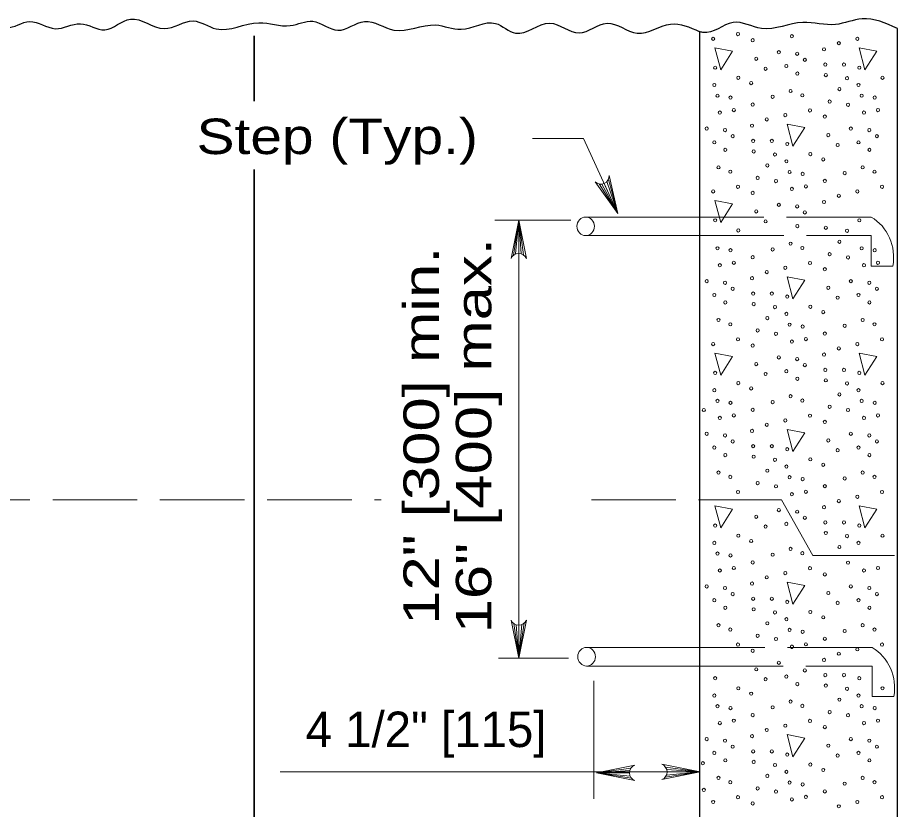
# Model space of a CAD drawing. Extents: x 1083.1 to 1117.1, y 697.4 to 719.4.
# Drawn here: x 1095.658 to 1099.53, y 707.048 to 710.532 of the extents above; entities that cross this region are included whole.
import ezdxf
from ezdxf.enums import TextEntityAlignment as Align

# ---------------------------------------------------------------- set-up
doc = ezdxf.new("R2010")
doc.units = 0
doc.header["$LTSCALE"] = 0.062
doc.linetypes.add('LONG_DASHED', pattern=[7.5, 6, -1.5])
doc.layers.add('1', color=7, linetype='Continuous', lineweight=13)

msp = doc.modelspace()

# ---------------------------------------------------------------- linework, layer by layer
at = {"layer": '1', "lineweight": 25}
for p, q in [((1098.65942, 710.471), (1098.65942, 703.65408)), ((1099.52967, 700.32125), (1099.52967, 710.48467))]:
    msp.add_line(p, q, dxfattribs=at)
at = {"layer": '1', "lineweight": 35}
for p, q in [((1096.69883, 710.45192), (1096.69883, 710.1645)), ((1096.69883, 709.86442), (1096.69883, 708.37567))]:
    msp.add_line(p, q, dxfattribs=at)
at = {"layer": '1'}
for p, q in [((1098.21767, 709.80017), (1098.30008, 709.67033)), ((1098.22942, 709.79983), (1098.30008, 709.67033)), ((1098.23983, 709.80292), (1098.30008, 709.67033)), ((1098.25117, 709.811), (1098.30008, 709.67033)), ((1098.25775, 709.82042), (1098.30008, 709.67033)), ((1098.65342, 709.65483), (1098.15775, 709.65483)), ((1097.75842, 709.64033), (1098.09217, 709.64033)), ((1097.83958, 709.48625), (1097.86317, 709.64033)), ((1097.8495, 709.49208), (1097.86317, 709.64033)), ((1097.86317, 709.49475), (1097.86317, 709.64033)), ((1097.87392, 709.49317), (1097.86317, 709.64033)), ((1097.8845, 709.488), (1097.86317, 709.64033)), ((1097.86317, 707.71325), (1097.86317, 709.64033)), ((1098.15775, 709.57283), (1098.65742, 709.57283)), ((1097.84183, 707.86558), (1097.86317, 707.71325)), ((1097.88675, 707.86733), (1097.86317, 707.71325)), ((1097.85242, 707.86042), (1097.86317, 707.71325)), ((1097.87683, 707.8615), (1097.86317, 707.71325)), ((1097.86317, 707.85883), (1097.86317, 707.71325)), ((1098.65942, 707.76092), (1098.16192, 707.76092)), ((1097.77383, 707.71325), (1098.082, 707.71325)), ((1098.16192, 707.67892), (1098.65533, 707.67892)), ((1098.19383, 707.09442), (1098.19383, 707.61367)), ((1096.81375, 707.21283), (1098.66158, 707.21283)), ((1098.35775, 707.22975), (1098.2055, 707.2085)), ((1098.35258, 707.21925), (1098.2055, 707.2085)), ((1098.35108, 707.2085), (1098.2055, 707.2085)), ((1098.35375, 707.19475), (1098.2055, 707.2085)), ((1098.35958, 707.18492), (1098.2055, 707.2085)), ((1098.5075, 707.18925), (1098.66158, 707.21283)), ((1098.50925, 707.23417), (1098.66158, 707.21283)), ((1098.51333, 707.19917), (1098.66158, 707.21283)), ((1098.51442, 707.22358), (1098.66158, 707.21283)), ((1098.516, 707.21283), (1098.66158, 707.21283))]:
    msp.add_line(p, q, dxfattribs=at)
at = {"layer": '1', "linetype": 'LONG_DASHED'}
for p, q in [((1099.41417, 709.65483), (1098.65342, 709.65483)), ((1098.65742, 709.57283), (1099.41417, 709.57283)), ((1094.39633, 708.41083), (1097.25833, 708.41083)), ((1098.18292, 708.41083), (1099.0195, 708.41083)), ((1099.0195, 708.41083), (1099.15725, 708.16475)), ((1099.15725, 708.16475), (1099.5175, 708.16475)), ((1099.41833, 707.76092), (1098.65942, 707.76092)), ((1098.65533, 707.67892), (1099.41833, 707.67892))]:
    msp.add_line(p, q, dxfattribs=at)
at = {"layer": '1'}
for points in [[(1098.72675, 710.39933), (1098.75242, 710.30208), (1098.80458, 710.38425)], [(1099.36117, 710.39933), (1099.38675, 710.30208), (1099.439, 710.38425)], [(1099.04392, 710.06358), (1099.06958, 709.96625), (1099.12183, 710.04842)], [(1098.72675, 709.72775), (1098.75242, 709.63033), (1098.80458, 709.71258)], [(1099.04392, 709.392), (1099.06958, 709.29458), (1099.12183, 709.37675)], [(1098.72675, 709.05608), (1098.75242, 708.95875), (1098.80458, 709.04092)], [(1099.36117, 709.05608), (1099.38675, 708.95875), (1099.439, 709.04092)], [(1099.04392, 708.72025), (1099.06958, 708.623), (1099.12183, 708.70517)], [(1098.72675, 708.3845), (1098.75242, 708.28717), (1098.80458, 708.36925)], [(1099.36117, 708.3845), (1099.38675, 708.28717), (1099.439, 708.36925)], [(1099.04392, 708.04867), (1099.06958, 707.95125), (1099.12183, 708.03342)], [(1099.04392, 707.377), (1099.06958, 707.27967), (1099.12183, 707.36183)]]:
    msp.add_lwpolyline(points, close=True, dxfattribs=at)
for points in [[(1098.30008, 709.67033), (1098.14858, 709.99992), (1097.92408, 709.99992)], [(1098.26108, 709.83742), (1098.30008, 709.67033), (1098.19983, 709.80958)], [(1097.8295, 709.47208), (1097.86317, 709.64033), (1097.89683, 709.47208)], [(1097.89683, 707.8815), (1097.86317, 707.71325), (1097.8295, 707.8815)], [(1098.49333, 707.17917), (1098.66158, 707.21283), (1098.49333, 707.2465)], [(1098.37367, 707.17483), (1098.2055, 707.2085), (1098.37367, 707.24208)]]:
    msp.add_lwpolyline(points, dxfattribs=at)
at = {"layer": '1', "linetype": 'LONG_DASHED'}
for points in [[(1099.41417, 709.57283), (1099.41417, 709.43892), (1099.50983, 709.43892)], [(1099.41833, 707.67892), (1099.41833, 707.545), (1099.514, 707.545)]]:
    msp.add_lwpolyline(points, dxfattribs=at)
at = {"layer": '1', "lineweight": 35}
msp.add_lwpolyline([(1096.69883, 708.37567), (1096.69883, 700.00317), (1096.69883, 699.45117)], dxfattribs=at)
at = {"layer": '1'}
for centre, start, end in [((1098.22483, 709.83586), 226.51945, 2.34557), ((1097.86321, 709.45851), 22.08782, 157.91395), ((1097.86313, 707.89506), 202.08782, 337.91395), ((1098.47974, 707.21286), 292.08605, 67.91218), ((1098.38728, 707.20851), 112.08782, 247.91395)]:
    msp.add_arc(centre, 0.03631, start, end, dxfattribs=at)
for centre, major_axis in [((1098.82781, 710.45979), (0, 0.00718)), ((1098.71906, 710.43891), (0, 0.00718)), ((1098.89294, 710.43259), (0, 0.00718)), ((1099.06534, 710.45011), (0, 0.00718)), ((1099.27205, 710.41988), (0, 0.00718)), ((1099.35346, 710.43891), (0, 0.00718)), ((1099.00771, 710.38003), (0, 0.00718)), ((1099.08855, 710.37304), (0, 0.00718)), ((1099.20702, 710.39268), (0, 0.00718)), ((1098.90838, 710.35098), (0, 0.00718)), ((1099.12222, 710.34645), (0, 0.00718)), ((1098.72763, 710.31197), (0, 0.00718)), ((1098.94951, 710.30744), (0, 0.00718)), ((1099.04113, 710.31925), (0, 0.00718)), ((1099.21215, 710.32557), (0, 0.00718)), ((1099.29441, 710.32557), (0, 0.00718)), ((1099.36203, 710.31197), (0, 0.00718)), ((1098.82955, 710.26753), (0, 0.00718)), ((1099.08939, 710.28628), (0, 0.00718)), ((1099.21469, 710.27934), (0, 0.00718)), ((1099.3081, 710.26574), (0, 0.00718)), ((1099.46395, 710.26753), (0, 0.00718)), ((1098.72419, 710.2358), (0, 0.00718)), ((1098.88607, 710.24397), (0, 0.00718)), ((1099.35859, 710.2358), (0, 0.00718)), ((1098.73793, 710.18867), (0, 0.00718)), ((1098.79529, 710.18044), (0, 0.00718)), ((1098.98059, 710.18385), (0, 0.00718)), ((1099.05942, 710.20921), (0, 0.00718)), ((1099.11165, 710.19018), (0, 0.00718)), ((1099.27464, 710.21766), (0, 0.00718)), ((1099.37234, 710.18867), (0, 0.00718)), ((1099.4297, 710.18044), (0, 0.00718)), ((1098.89294, 710.1496), (0, 0.00718)), ((1099.23155, 710.16298), (0, 0.00718)), ((1099.31233, 710.14876), (0, 0.00718)), ((1098.74814, 710.11428), (0, 0.00718)), ((1098.80983, 710.1252), (0, 0.00718)), ((1099.03626, 710.10309), (0, 0.00718)), ((1099.14501, 710.12397), (0, 0.00718)), ((1099.38254, 710.11428), (0, 0.00718)), ((1099.44424, 710.1252), (0, 0.00718)), ((1098.95485, 710.08406), (0, 0.00718)), ((1099.21014, 710.09676), (0, 0.00718)), ((1098.69051, 710.04421), (0, 0.00718)), ((1098.77135, 710.03721), (0, 0.00718)), ((1098.88982, 710.05686), (0, 0.00718)), ((1099.32491, 710.04421), (0, 0.00718)), ((1099.40575, 710.03721), (0, 0.00718)), ((1098.80502, 710.01062), (0, 0.00718)), ((1098.89495, 709.98975), (0, 0.00718)), ((1098.97721, 709.98975), (0, 0.00718)), ((1099.22558, 710.01516), (0, 0.00718)), ((1099.43942, 710.01062), (0, 0.00718)), ((1098.72392, 709.98342), (0, 0.00718)), ((1098.77219, 709.95046), (0, 0.00718)), ((1099.04483, 709.97615), (0, 0.00718)), ((1099.26671, 709.97161), (0, 0.00718)), ((1099.35833, 709.98342), (0, 0.00718)), ((1099.40659, 709.95046), (0, 0.00718)), ((1098.89749, 709.94352), (0, 0.00718)), ((1098.9909, 709.92991), (0, 0.00718)), ((1099.14675, 709.93171), (0, 0.00718)), ((1098.74222, 709.87338), (0, 0.00718)), ((1098.95744, 709.88184), (0, 0.00718)), ((1099.04139, 709.89997), (0, 0.00718)), ((1099.20327, 709.90814), (0, 0.00718)), ((1099.37662, 709.87338), (0, 0.00718)), ((1098.79445, 709.85435), (0, 0.00718)), ((1099.05514, 709.85284), (0, 0.00718)), ((1099.1125, 709.84462), (0, 0.00718)), ((1099.29779, 709.84803), (0, 0.00718)), ((1099.42885, 709.85435), (0, 0.00718)), ((1098.91435, 709.82715), (0, 0.00718)), ((1098.99513, 709.81294), (0, 0.00718)), ((1099.21014, 709.81378), (0, 0.00718)), ((1098.71906, 709.76726), (0, 0.00718)), ((1098.82781, 709.78814), (0, 0.00718)), ((1098.89294, 709.76094), (0, 0.00718)), ((1099.06534, 709.77846), (0, 0.00718)), ((1099.12703, 709.78937), (0, 0.00718)), ((1099.35346, 709.76726), (0, 0.00718)), ((1099.46221, 709.78814), (0, 0.00718)), ((1099.20702, 709.72103), (0, 0.00718)), ((1099.27205, 709.74823), (0, 0.00718)), ((1098.90838, 709.67933), (0, 0.00718)), ((1099.00771, 709.70838), (0, 0.00718)), ((1099.08855, 709.70139), (0, 0.00718)), ((1098.15771, 709.61383), (0, -0.041)), ((1098.72763, 709.64032), (0, 0.00718)), ((1099.12222, 709.6748), (0, 0.00718)), ((1099.36203, 709.64032), (0, 0.00718)), ((1098.94951, 709.63579), (0, 0.00718)), ((1099.08939, 709.61463), (0, 0.00718)), ((1099.21469, 709.60769), (0, 0.00718)), ((1098.82955, 709.59588), (0, 0.00718)), ((1099.3081, 709.59409), (0, 0.00718)), ((1099.05942, 709.53756), (0, 0.00718)), ((1099.27464, 709.54601), (0, 0.00718)), ((1098.73793, 709.51702), (0, 0.00718)), ((1098.79529, 709.50879), (0, 0.00718)), ((1098.98059, 709.51221), (0, 0.00718)), ((1099.11165, 709.51853), (0, 0.00718)), ((1099.23155, 709.49133), (0, 0.00718)), ((1099.37234, 709.51702), (0, 0.00718)), ((1099.4297, 709.50879), (0, 0.00718)), ((1098.80983, 709.45355), (0, 0.00718)), ((1098.89294, 709.47795), (0, 0.00718)), ((1099.14501, 709.45232), (0, 0.00718)), ((1099.31233, 709.47711), (0, 0.00718)), ((1099.44424, 709.45355), (0, 0.00718)), ((1098.74814, 709.44263), (0, 0.00718)), ((1098.95485, 709.41241), (0, 0.00718)), ((1099.03626, 709.43144), (0, 0.00718)), ((1099.21014, 709.42511), (0, 0.00718)), ((1099.38254, 709.44263), (0, 0.00718)), ((1098.69051, 709.37256), (0, 0.00718)), ((1098.88982, 709.38521), (0, 0.00718)), ((1099.32491, 709.37256), (0, 0.00718)), ((1098.77135, 709.36556), (0, 0.00718)), ((1098.80502, 709.33898), (0, 0.00718)), ((1099.22558, 709.34351), (0, 0.00718)), ((1099.40575, 709.36556), (0, 0.00718)), ((1099.43942, 709.33898), (0, 0.00718)), ((1098.72392, 709.31177), (0, 0.00718)), ((1098.89495, 709.3181), (0, 0.00718)), ((1098.97721, 709.3181), (0, 0.00718)), ((1099.04483, 709.3045), (0, 0.00718)), ((1099.26671, 709.29996), (0, 0.00718)), ((1099.35833, 709.31177), (0, 0.00718)), ((1098.77219, 709.27881), (0, 0.00718)), ((1098.89749, 709.27187), (0, 0.00718)), ((1098.9909, 709.25827), (0, 0.00718)), ((1099.14675, 709.26006), (0, 0.00718)), ((1099.40659, 709.27881), (0, 0.00718)), ((1099.04139, 709.22832), (0, 0.00718)), ((1099.20327, 709.23649), (0, 0.00718)), ((1098.74222, 709.20174), (0, 0.00718)), ((1098.79445, 709.18271), (0, 0.00718)), ((1098.95744, 709.21019), (0, 0.00718)), ((1099.05514, 709.18119), (0, 0.00718)), ((1099.1125, 709.17297), (0, 0.00718)), ((1099.29779, 709.17638), (0, 0.00718)), ((1099.37662, 709.20174), (0, 0.00718)), ((1099.42885, 709.18271), (0, 0.00718)), ((1098.91435, 709.1555), (0, 0.00718)), ((1098.99513, 709.14129), (0, 0.00718)), ((1099.21014, 709.14213), (0, 0.00718)), ((1098.71906, 709.09561), (0, 0.00718)), ((1098.82781, 709.11649), (0, 0.00718)), ((1099.06534, 709.10681), (0, 0.00718)), ((1099.12703, 709.11772), (0, 0.00718)), ((1099.35346, 709.09561), (0, 0.00718)), ((1099.46221, 709.11649), (0, 0.00718)), ((1098.89294, 709.08929), (0, 0.00718)), ((1099.27205, 709.07658), (0, 0.00718)), ((1099.00771, 709.03673), (0, 0.00718)), ((1099.08855, 709.02974), (0, 0.00718)), ((1099.20702, 709.04938), (0, 0.00718)), ((1098.90838, 709.00768), (0, 0.00718)), ((1099.12222, 709.00315), (0, 0.00718)), ((1099.21215, 708.98227), (0, 0.00718)), ((1099.29441, 708.98227), (0, 0.00718)), ((1098.72763, 708.96867), (0, 0.00718)), ((1098.94951, 708.96414), (0, 0.00718)), ((1099.04113, 708.97595), (0, 0.00718)), ((1099.08939, 708.94298), (0, 0.00718)), ((1099.36203, 708.96867), (0, 0.00718)), ((1098.82955, 708.92423), (0, 0.00718)), ((1099.21469, 708.93604), (0, 0.00718)), ((1099.3081, 708.92244), (0, 0.00718)), ((1099.46395, 708.92423), (0, 0.00718)), ((1098.72419, 708.8925), (0, 0.00718)), ((1098.88607, 708.90067), (0, 0.00718)), ((1099.05942, 708.86591), (0, 0.00718)), ((1099.27464, 708.87436), (0, 0.00718)), ((1099.35859, 708.8925), (0, 0.00718)), ((1098.73793, 708.84537), (0, 0.00718)), ((1098.79529, 708.83714), (0, 0.00718)), ((1098.98059, 708.84056), (0, 0.00718)), ((1099.11165, 708.84688), (0, 0.00718)), ((1099.37234, 708.84537), (0, 0.00718)), ((1099.4297, 708.83714), (0, 0.00718)), ((1098.67793, 708.80546), (0, 0.00718)), ((1098.89294, 708.8063), (0, 0.00718)), ((1099.23155, 708.81968), (0, 0.00718)), ((1099.31233, 708.80546), (0, 0.00718)), ((1098.74814, 708.77098), (0, 0.00718)), ((1098.80983, 708.7819), (0, 0.00718)), ((1099.03626, 708.75979), (0, 0.00718)), ((1099.14501, 708.78067), (0, 0.00718)), ((1099.21014, 708.75347), (0, 0.00718)), ((1099.38254, 708.77098), (0, 0.00718)), ((1099.44424, 708.7819), (0, 0.00718)), ((1098.88982, 708.71356), (0, 0.00718)), ((1098.95485, 708.74076), (0, 0.00718)), ((1098.69051, 708.70091), (0, 0.00718)), ((1098.77135, 708.69391), (0, 0.00718)), ((1099.22558, 708.67186), (0, 0.00718)), ((1099.32491, 708.70091), (0, 0.00718)), ((1099.40575, 708.69391), (0, 0.00718)), ((1098.72392, 708.64012), (0, 0.00718)), ((1098.80502, 708.66733), (0, 0.00718)), ((1098.89495, 708.64645), (0, 0.00718)), ((1098.97721, 708.64645), (0, 0.00718)), ((1099.04483, 708.63285), (0, 0.00718)), ((1099.35833, 708.64012), (0, 0.00718)), ((1099.43942, 708.66733), (0, 0.00718)), ((1098.77219, 708.60716), (0, 0.00718)), ((1098.89749, 708.60022), (0, 0.00718)), ((1099.26671, 708.62831), (0, 0.00718)), ((1099.40659, 708.60716), (0, 0.00718)), ((1098.9909, 708.58662), (0, 0.00718)), ((1099.04139, 708.55667), (0, 0.00718)), ((1099.14675, 708.58841), (0, 0.00718)), ((1099.20327, 708.56484), (0, 0.00718)), ((1098.74222, 708.53009), (0, 0.00718)), ((1098.95744, 708.53854), (0, 0.00718)), ((1099.37662, 708.53009), (0, 0.00718)), ((1098.79445, 708.51106), (0, 0.00718)), ((1098.91435, 708.48385), (0, 0.00718)), ((1099.05514, 708.50954), (0, 0.00718)), ((1099.1125, 708.50132), (0, 0.00718)), ((1099.29779, 708.50473), (0, 0.00718)), ((1099.42885, 708.51106), (0, 0.00718)), ((1098.82781, 708.44484), (0, 0.00718)), ((1098.99513, 708.46964), (0, 0.00718)), ((1099.12703, 708.44607), (0, 0.00718)), ((1099.21014, 708.47048), (0, 0.00718)), ((1099.46221, 708.44484), (0, 0.00718)), ((1099.06534, 708.43516), (0, 0.00718)), ((1099.27205, 708.40494), (0, 0.00718)), ((1099.35346, 708.42397), (0, 0.00718)), ((1099.00771, 708.36508), (0, 0.00718)), ((1099.20702, 708.37773), (0, 0.00718)), ((1098.90838, 708.33604), (0, 0.00718)), ((1099.08855, 708.35809), (0, 0.00718)), ((1099.12222, 708.3315), (0, 0.00718)), ((1098.72763, 708.29702), (0, 0.00718)), ((1098.94951, 708.29249), (0, 0.00718)), ((1099.04113, 708.3043), (0, 0.00718)), ((1099.21215, 708.31062), (0, 0.00718)), ((1099.29441, 708.31062), (0, 0.00718)), ((1099.36203, 708.29702), (0, 0.00718)), ((1098.82955, 708.25258), (0, 0.00718)), ((1099.21469, 708.26439), (0, 0.00718)), ((1099.3081, 708.25079), (0, 0.00718)), ((1099.46395, 708.25258), (0, 0.00718)), ((1098.72419, 708.22085), (0, 0.00718)), ((1098.88607, 708.22902), (0, 0.00718)), ((1099.35859, 708.22085), (0, 0.00718)), ((1098.73793, 708.17372), (0, 0.00718)), ((1098.98059, 708.16891), (0, 0.00718)), ((1099.05942, 708.19426), (0, 0.00718)), ((1099.11165, 708.17523), (0, 0.00718)), ((1099.27464, 708.20271), (0, 0.00718)), ((1098.79529, 708.16549), (0, 0.00718)), ((1098.89294, 708.13465), (0, 0.00718)), ((1099.31233, 708.13381), (0, 0.00718)), ((1098.74814, 708.09934), (0, 0.00718)), ((1098.80983, 708.11025), (0, 0.00718)), ((1099.14501, 708.10902), (0, 0.00718)), ((1099.38254, 708.09934), (0, 0.00718)), ((1099.44424, 708.11025), (0, 0.00718)), ((1098.95485, 708.06911), (0, 0.00718)), ((1099.03626, 708.08814), (0, 0.00718)), ((1099.21014, 708.08182), (0, 0.00718)), ((1098.69051, 708.02926), (0, 0.00718)), ((1098.77135, 708.02226), (0, 0.00718)), ((1098.88982, 708.04191), (0, 0.00718)), ((1099.32491, 708.02926), (0, 0.00718)), ((1099.40575, 708.02226), (0, 0.00718)), ((1098.80502, 707.99568), (0, 0.00718)), ((1098.89495, 707.9748), (0, 0.00718)), ((1098.97721, 707.9748), (0, 0.00718)), ((1099.22558, 708.00021), (0, 0.00718)), ((1099.43942, 707.99568), (0, 0.00718)), ((1098.72392, 707.96848), (0, 0.00718)), ((1098.77219, 707.93551), (0, 0.00718)), ((1099.04483, 707.9612), (0, 0.00718)), ((1099.26671, 707.95667), (0, 0.00718)), ((1099.35833, 707.96848), (0, 0.00718)), ((1099.40659, 707.93551), (0, 0.00718)), ((1098.89749, 707.92857), (0, 0.00718)), ((1098.9909, 707.91497), (0, 0.00718)), ((1099.14675, 707.91676), (0, 0.00718)), ((1098.74222, 707.85844), (0, 0.00718)), ((1098.95744, 707.86689), (0, 0.00718)), ((1099.04139, 707.88502), (0, 0.00718)), ((1099.20327, 707.89319), (0, 0.00718)), ((1099.37662, 707.85844), (0, 0.00718)), ((1098.79445, 707.83941), (0, 0.00718)), ((1099.05514, 707.8379), (0, 0.00718)), ((1099.1125, 707.82967), (0, 0.00718)), ((1099.29779, 707.83308), (0, 0.00718)), ((1099.42885, 707.83941), (0, 0.00718)), ((1098.91435, 707.81221), (0, 0.00718)), ((1098.99513, 707.79799), (0, 0.00718)), ((1099.21014, 707.79883), (0, 0.00718)), ((1098.16189, 707.7199), (0, -0.041)), ((1098.82781, 707.77319), (0, 0.00718)), ((1098.89294, 707.74599), (0, 0.00718)), ((1099.12703, 707.77442), (0, 0.00718)), ((1099.35346, 707.75232), (0, 0.00718)), ((1099.46221, 707.77319), (0, 0.00718)), ((1099.20702, 707.70608), (0, 0.00718)), ((1099.27205, 707.73329), (0, 0.00718)), ((1098.90838, 707.66439), (0, 0.00718)), ((1099.00771, 707.69344), (0, 0.00718)), ((1098.72763, 707.62537), (0, 0.00718)), ((1099.04113, 707.63265), (0, 0.00718)), ((1099.12222, 707.65985), (0, 0.00718)), ((1099.21215, 707.63898), (0, 0.00718)), ((1099.29441, 707.63898), (0, 0.00718)), ((1099.36203, 707.62537), (0, 0.00718)), ((1098.94951, 707.62084), (0, 0.00718)), ((1099.08939, 707.59968), (0, 0.00718)), ((1099.21469, 707.59274), (0, 0.00718)), ((1098.72419, 707.5492), (0, 0.00718)), ((1098.82955, 707.58093), (0, 0.00718)), ((1098.88607, 707.55737), (0, 0.00718)), ((1099.3081, 707.57914), (0, 0.00718)), ((1099.35859, 707.5492), (0, 0.00718)), ((1099.46395, 707.58093), (0, 0.00718)), ((1099.05942, 707.52261), (0, 0.00718)), ((1099.27464, 707.53106), (0, 0.00718)), ((1098.73793, 707.50207), (0, 0.00718)), ((1098.79529, 707.49384), (0, 0.00718)), ((1098.98059, 707.49726), (0, 0.00718)), ((1099.11165, 707.50358), (0, 0.00718)), ((1099.23155, 707.47638), (0, 0.00718)), ((1099.37234, 707.50207), (0, 0.00718)), ((1099.4297, 707.49384), (0, 0.00718)), ((1098.80983, 707.4386), (0, 0.00718)), ((1098.89294, 707.463), (0, 0.00718)), ((1099.14501, 707.43737), (0, 0.00718)), ((1099.31233, 707.46216), (0, 0.00718)), ((1099.44424, 707.4386), (0, 0.00718)), ((1098.74814, 707.42769), (0, 0.00718)), ((1098.95485, 707.39746), (0, 0.00718)), ((1099.03626, 707.41649), (0, 0.00718)), ((1099.21014, 707.41017), (0, 0.00718)), ((1099.38254, 707.42769), (0, 0.00718)), ((1098.69051, 707.35761), (0, 0.00718)), ((1098.88982, 707.37026), (0, 0.00718)), ((1099.32491, 707.35761), (0, 0.00718)), ((1098.77135, 707.35061), (0, 0.00718)), ((1098.80502, 707.32403), (0, 0.00718)), ((1099.22558, 707.32856), (0, 0.00718)), ((1099.40575, 707.35061), (0, 0.00718)), ((1099.43942, 707.32403), (0, 0.00718)), ((1098.72392, 707.29683), (0, 0.00718)), ((1098.89495, 707.30315), (0, 0.00718)), ((1098.97721, 707.30315), (0, 0.00718)), ((1099.04483, 707.28955), (0, 0.00718)), ((1099.26671, 707.28502), (0, 0.00718)), ((1099.35833, 707.29683), (0, 0.00718)), ((1098.6737, 707.25095), (0, 0.00718)), ((1098.77219, 707.26386), (0, 0.00718)), ((1098.89749, 707.25692), (0, 0.00718)), ((1098.9909, 707.24332), (0, 0.00718)), ((1099.14675, 707.24511), (0, 0.00718)), ((1099.40659, 707.26386), (0, 0.00718)), ((1099.04139, 707.21337), (0, 0.00718)), ((1099.20327, 707.22155), (0, 0.00718)), ((1098.74222, 707.18679), (0, 0.00718)), ((1098.79445, 707.16776), (0, 0.00718)), ((1098.95744, 707.19524), (0, 0.00718)), ((1099.05514, 707.16625), (0, 0.00718)), ((1099.29779, 707.16143), (0, 0.00718)), ((1099.37662, 707.18679), (0, 0.00718)), ((1099.42885, 707.16776), (0, 0.00718)), ((1098.67793, 707.13398), (0, 0.00718)), ((1098.91435, 707.14056), (0, 0.00718)), ((1098.99513, 707.12634), (0, 0.00718)), ((1099.1125, 707.15802), (0, 0.00718)), ((1099.21014, 707.12718), (0, 0.00718)), ((1098.82781, 707.10154), (0, 0.00718)), ((1099.06534, 707.09186), (0, 0.00718)), ((1099.12703, 707.10278), (0, 0.00718)), ((1099.46221, 707.10154), (0, 0.00718)), ((1098.71906, 707.08067), (0, 0.00718)), ((1098.89294, 707.07434), (0, 0.00718)), ((1099.27205, 707.06164), (0, 0.00718)), ((1099.35346, 707.08067), (0, 0.00718))]:
    msp.add_ellipse(centre, major_axis=major_axis, ratio=0.944544, dxfattribs=at)
at = {"layer": '1', "linetype": 'LONG_DASHED'}
for centre in [(1099.32145, 709.47706), (1099.32563, 707.58312)]:
    msp.add_ellipse(centre, major_axis=(0, -0.20306), ratio=0.944544, start_param=1.3817766, end_param=2.6372404, dxfattribs=at)
msp.add_ellipse((1099.06534, 707.76351), major_axis=(0, 0.00718), ratio=0.944544, dxfattribs=at)
at = {"layer": '1', "lineweight": 25}
for points in [[(1094.78833, 710.5125), (1094.86758, 710.49192), (1095.00183, 710.51783), (1095.11458, 710.47258), (1095.26925, 710.51717), (1095.382, 710.47667), (1095.49667, 710.52592), (1095.60942, 710.4875), (1095.711, 710.51525), (1095.82367, 710.48358), (1095.93467, 710.5055), (1096.04175, 710.47867), (1096.15458, 710.526), (1096.30275, 710.48383), (1096.43042, 710.5175), (1096.53192, 710.48283), (1096.71933, 710.51), (1096.85817, 710.497), (1096.957, 710.516), (1097.06775, 710.4765), (1097.18433, 710.51508), (1097.31383, 710.47767), (1097.49742, 710.49992), (1097.61017, 710.48092), (1097.76117, 710.50692), (1097.84967, 710.4635), (1097.99975, 710.50808), (1098.12925, 710.46475), (1098.25225, 710.50725), (1098.38458, 710.46392), (1098.53183, 710.50358), (1098.65775, 710.47125)], [(1099.52967, 710.48467), (1099.37425, 710.527), (1099.25783, 710.502), (1099.11333, 710.51117), (1098.93158, 710.48492), (1098.80675, 710.51075), (1098.6735, 710.46717), (1098.65775, 710.47125)]]:
    msp.add_spline(points, degree=3, dxfattribs=at)

# ---------------------------------------------------------------- texts
at = {"layer": '1', "width": 1.2}
msp.add_text('Step (Typ.)', height=0.156, dxfattribs=at).set_placement((1096.44558, 709.93183))
at = {"layer": '1', "width": 1.3}
for s, p in [('16" [400] max.', (1097.74275, 708.69233)), ('12" [300] min.', (1097.512, 708.69237))]:
    msp.add_text(s, height=0.156, rotation=90, dxfattribs=at).set_placement(p, align=Align.CENTER)
at = {"layer": '1'}
msp.add_text('4 1/2" [115]', height=0.156, dxfattribs=at).set_placement((1097.45546, 707.32242), align=Align.CENTER)

doc.saveas('drawing.dxf')
